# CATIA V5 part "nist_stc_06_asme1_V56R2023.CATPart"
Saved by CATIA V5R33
Part number: NIST PMI STC 06 ASME1
Revision: D
Description: NIST PMI test model downloaded from http://go.usa.gov/mGVm
Bounding box of the stored display mesh (mm): x -152.4 to 152.4, y 0 to 97.79, z -247.65 to 0
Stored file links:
  C:\Users\rla3\OneDrive - NIST\STEP\NIST Test Models\CAx Test Rounds Data\R53J\NIST Files\nist_stc_06_asme1_V56R2023.CATPart
  E:\users\dgn\TPS V5\Import-export annotations\Step\PMI representation 2015\NIST UC\nist_ftc_06_asme1_ct5240_rd.CATPart
  E:\users\dgn\TPS V5\Import-export annotations\Step\PMI representation 2015\NIST UC\CVDHoleParallelCountersink_1_TAG.CATPart
  E:\users\dgn\TPS V5\Import-export annotations\Step\PMI representation 2015\NIST UC\TS_CounterboredHole.CATPart
  C:\Program Files\Dassault Systemes\B32\win_b64\resources\graphic\CATTPSGeneralTolerance.xlsx
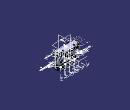
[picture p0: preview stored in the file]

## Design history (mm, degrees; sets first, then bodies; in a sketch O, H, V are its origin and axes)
TTRSSet1
f4a2d38f3ddc11d3a929006094b99c4b_11 "CATTPSSet"
Set1 "Geom_for_MBD_A_notes"
  Plane1: type Equation, A -0.57735, B -0.57735, C 0.57735, Length 229.55, RefPoint vertex [face of Pad1 from Sketch11.L1 | face of Pad1 from Sketch11.L2 | end face of Pad1], RefAxis AxisSystem5
Set2 "MBD_A"
  AxisSystem1 "F1": origin (108.585, 50.8, -209.55), X (-1, 0, 0), Y (0, 1, 0), Z (0, 0, -1)
  AxisSystem2 "F2": origin (36.195, 50.8, -209.55), X (-1, 0, 0), Y (0, 1, 0), Z (0, 0, -1)
  AxisSystem3 "F3": origin (-36.195, 50.8, -209.55), X (-1, 0, 0), Y (0, 1, 0), Z (0, 0, -1)
  AxisSystem4 "F4": origin (-108.585, 50.8, -209.55), X (-1, 0, 0), Y (0, 1, 0), Z (0, 0, -1)
  AxisSystem5 "EAB": origin (0, 0, -209.55), X (-1, 0, 0), Y (0, 0, 1), Z (0, 1, 0)
Set3 "MBD_C"
  AxisSystem6 "DCJ": origin (82.55, 31.75, 0), X (1, 0, 0), Y (0, 0, -1), Z (0, 1, 0)
  AxisSystem7 "DCK": origin (-82.55, 31.75, 0), X (1, 0, 0), Y (0, 0, -1), Z (0, 1, 0)
  AxisSystem8 "DG": origin (76.2, 31.75, -158.75), X (0, 0, -1), Y (-1, 0, 0), Z (0, 1, 0)
  AxisSystem9 "DH": origin (-76.2, 31.75, -158.75), X (0, 0, -1), Y (-1, 0, 0), Z (0, 1, 0)
  Sketch1 on face of Pocket1 from Sketch14.L6, origin (-87.885, 40.9814, 0), H (-0.4226, -0.9063, 0), V (0, 0, 1)
    line L1 (-45.8598, -31.75) -> (-45.8598, 0)
    point P1 (-45.8598, -31.75)
    reference projected point E1 (-45.8598, -31.75) from Sketch9.P5
    vertical: L1 V
    coincidence: P1 E1
  Sketch2 on face of RectPattern2, origin (87.885, 40.9814, 0), H (-0.4226, 0.9063, 0), V (0, 0, 1)
    line L1 (45.8598, -31.75) -> (45.8598, 0)
    point P1 (45.8598, -31.75)
    reference projected point E1 (45.8598, -31.75) from Sketch8.P6
    vertical: L1 V
    coincidence: P1 E1
  Sketch3 on face of RectPattern2, origin (47.7271, -22.2555, 0), H (-0.4226, -0.9063, 0), V (0, 0, 1)
    line L1 (-115.6341, -31.75) -> (-115.6341, 0)
    point P1 (-115.6341, -31.75)
    reference projected point E1 (-115.6341, -31.75) from Sketch8.P5
    vertical: L1 V
    coincidence: P1 E1
  Sketch4 on face of RectPattern2, origin (47.7271, -22.2555, 0), H (-0.4226, -0.9063, 0), V (0, 0, 1)
    projected line E1 (-132.4556, 0) -> (-97.4233, 0) from edge [face of RectPattern2 | face of Pad1 from Sketch11.L1]
    projected line E2 (-132.4556, -31.75) -> (-97.4233, -31.75) from edge [face of Pad1 from Sketch11.L7 | face of RectPattern2]
    line L1 (-97.4233, 0) -> (-115.6341, 0)
    point P5 (-114.9395, 0)
    line L2 (-115.6341, -31.75) -> (-97.4233, -31.75)
    point P6 (-115.6341, -31.75)
    line L3 (-97.4233, 0) -> (-97.4233, -31.75)
    line L4 (-115.6341, 0) -> (-115.6341, -31.75)
    reference projected line E3 (-115.6341, -31.75) -> (-115.6341, 0) from Sketch3
    midpoint: P5 E1
    horizontal: L1 H, L2 H
    coincidence: P6 E2, E3 L4
    vertical: L3 V, L4 V
  Sketch5 on face of RectPattern2, origin (87.885, 40.9814, 0), H (-0.4226, 0.9063, 0), V (0, 0, 1)
    projected line E1 (62.6813, 0) -> (27.6491, 0) from edge [face of Pad1 from Sketch11.L1 | face of RectPattern2]
    projected line E2 (45.8598, 0) -> (27.6491, 0) from edge [face of Pad1 from Sketch11.L1 | face of RectPattern2]
    projected line E3 (27.6491, -31.75) -> (27.6491, 0) from edge [face of RectPattern2 | face of RectPattern2]
    projected line E4 (27.6491, -31.75) -> (62.6813, -31.75) from edge [face of Pad1 from Sketch11.L7 | face of RectPattern2]
    projected line E5 (27.6491, -31.75) -> (45.8598, -31.75) from edge [face of Pad1 from Sketch11.L7 | face of RectPattern2]
    projected line E6 (45.8598, -31.75) -> (45.8598, 0) from Sketch2.L1
  Sketch6 on face of Pocket1 from Sketch14.L6, origin (-87.885, 40.9814, 0), H (-0.4226, -0.9063, 0), V (0, 0, 1)
    projected line E1 (-62.6813, 0) -> (-27.6491, 0) from edge [face of Pocket1 from Sketch14.L6 | face of Pad1 from Sketch11.L1]
    projected line E2 (-45.8598, 0) -> (-27.6491, 0) from edge [face of Pocket1 from Sketch14.L6 | face of Pad1 from Sketch11.L1]
    projected line E3 (-62.6813, -31.75) -> (-27.6491, -31.75) from edge [face of Pad1 from Sketch11.L7 | face of Pocket1 from Sketch14.L6]
    projected line E4 (-45.8598, -31.75) -> (-27.6491, -31.75) from edge [face of Pad1 from Sketch11.L7 | face of Pocket1 from Sketch14.L6]
    projected line E5 (-27.6491, -31.75) -> (-27.6491, 0) from edge [face of Pocket1 from Sketch14.L5 | face of Pocket1 from Sketch14.L6]
    projected line E6 (-45.8598, -31.75) -> (-45.8598, 0) from Sketch1.L1
  Sketch7 on face of Pocket1 from Sketch14.L1, origin (-47.7271, -22.2555, 0), H (-0.4226, 0.9063, 0), V (0, 0, 1)
    projected line E1 (97.4233, -31.75) -> (132.4556, -31.75) from edge [face of Pad1 from Sketch11.L7 | face of Pocket1 from Sketch14.L1]
    projected line E2 (97.4233, -31.75) -> (115.6341, -31.75) from edge [face of Pad1 from Sketch11.L7 | face of Pocket1 from Sketch14.L1]
    projected line E3 (97.4233, -31.75) -> (97.4233, 0) from edge [face of Pocket1 from Sketch14.L1 | face of Pocket1 from Sketch14.L2]
    projected line E4 (132.4556, 0) -> (97.4233, 0) from edge [face of Pad1 from Sketch11.L1 | face of Pocket1 from Sketch14.L1]
    projected line E5 (115.6341, 0) -> (97.4233, 0) from edge [face of Pad1 from Sketch11.L1 | face of Pocket1 from Sketch14.L1]
    projected line E6 (115.6341, -31.75) -> (115.6341, 0) from Sketch10.L1
    construction line L1 through (0, 0) direction (0, 1)
  Sketch8 on face of Pad1 from Sketch11.L7, origin (0, 0, -31.75), H (1, 0, 0), V (0, -1, 0)
    projected line E1 (103.7053, -97.79) -> (88.9, -66.04) from edge [face of Pad1 from Sketch11.L7 | face of RectPattern2]
    projected line E2 (76.2, -66.04) -> (61.3947, -97.79) from edge [face of Pad1 from Sketch11.L7 | face of RectPattern2]
    line L1 (88.9, -66.04) -> (76.2, -66.04)
    line L2 (96.5962, -82.5446) -> (68.5038, -82.5446)
    point P5 (96.5962, -82.5446)
    point P6 (68.5038, -82.5446)
    point P7 (96.5962, -82.5446)
    point P8 (68.5038, -82.5446)
    length L2 = 28.0924
    horizontal: L1 H, L2 H
    coincidence: P5 E1, P6 E2, P7 P5, P8 P6
  Sketch9 on face of Pad1 from Sketch11.L7, origin (0, 0, -31.75), H (1, 0, 0), V (0, -1, 0)
    projected line E1 (-61.3947, -97.79) -> (-76.2, -66.04) from edge [face of Pad1 from Sketch11.L7 | face of Pocket1 from Sketch14.L6]
    projected line E2 (-88.9, -66.04) -> (-103.7053, -97.79) from edge [face of Pad1 from Sketch11.L7 | face of Pocket1 from Sketch14.L1]
    line L1 (-76.2, -66.04) -> (-88.9, -66.04)
    line L2 (-68.5038, -82.5446) -> (-96.5962, -82.5446)
    point P5 (-68.5038, -82.5446)
    point P6 (-96.5962, -82.5446)
    point P7 (-68.5038, -82.5446)
    point P8 (-96.5962, -82.5446)
    length L2 = 28.0924
    horizontal: L1 H, L2 H
    coincidence: P5 E1, P7 P5, P6 E2, P8 P6
  Sketch10 on face of Pocket1 from Sketch14.L1, origin (-47.7271, -22.2555, 0), H (-0.4226, 0.9063, 0), V (0, 0, 1)
    line L1 (115.6341, -31.75) -> (115.6341, 0)
    point P1 (115.6341, -31.75)
    reference projected point E1 (115.6341, -31.75) from Sketch9.P6
    vertical: L1 V
    coincidence: P1 E1
Set4 "MBD_A_B_C"
  AxisSystem10 "DBC": origin (0, 31.75, 0), X (1, 0, 0), Y (0, 0, -1), Z (0, 1, 0)
  AxisSystem11 "ABC": origin (0, 0, 0), X (1, 0, 0), Y (0, 0, -1), Z (0, 1, 0)
Set5
  Plane2: type Offset, RefPlane xy-plane, Offset 247.65, reversed
  Plane3: type Offset, RefPlane zx-plane, Offset 46.99
  Plane4: type Offset, RefPlane yz-plane, Offset 76.2
  Plane5: type Offset, RefPlane yz-plane, Offset 114.3
  Point1: type OnCurve, Support edge [face of Pad1 from Sketch11.L7 | face of Pocket1 from Sketch14.L1], Length 18.2093
  Point2: type OnCurve, Support edge [face of Pad1 from Sketch11.L7 | face of Pocket1 from Sketch14.L6], Length 18.2093
  Point3: type OnCurve, Support edge [face of Pad1 from Sketch11.L7 | face of RectPattern2], Length 18.2093
  Point4: type OnCurve, Support edge [face of Pad1 from Sketch11.L7 | face of RectPattern2], Length 18.2093
  Plane6: type Offset, RefPlane zx-plane, Offset 66.04
  Plane7: type Angle, RefPlane xy-plane, Direction edge [face of Pad1 from Sketch11.L2 | face of Pad1 from Sketch11.L1], Angle 45
  Point5: type OnCurve, Support edge [face of Pad1 from Sketch11.L2 | face of Pad1 from Sketch11.L1], Length 152.4
  Point6: type OnPlane, Support face of Pad1 from Sketch11.L6, H 0, V 0, Direction (-1, 0, 0)
  Point7: type OnCurve, Support edge [face of Fillet1 | face of Pad1 from Sketch11.L6], RefPoint {extremum Reference edge [face of Fillet1 | face of Pad1 from Sketch11.L6], Direction (1, 2, 3)}, Length 65.977
  Point8: type OnCurve, Support edge [face of Fillet1 | face of Pad1 from Sketch11.L6], RefPoint {extremum Reference edge [face of Fillet1 | face of Pad1 from Sketch11.L6], Direction (1, 2, 3)}, Length 65.9892
  Point9: type OnPlane, Support face of Pad1 from Sketch11.L1, H 82.55, V 31.75, Direction (1, 0, 0)
  Point10: type OnPlane, Support face of Pad1 from Sketch11.L1, H -82.55, V 31.75, Direction (1, 0, 0)
  Plane8: type Offset, RefPlane face of Pad1 from Sketch11.L2, Offset 66.04
  Point11: type OnSurface, Support face of Fillet1, Length 0, Direction (-0.9567, 0.021, -0.2904)
  Plane9: type Offset, RefPlane face of Pad1 from Sketch11.L1, Offset 107.95
  Point12: type OnPlane, Support face of Pad1 from Sketch11.L6, H -76.2, V -158.75, Direction (-1, 0, 0)
  Point13: type OnPlane, Support face of Pad1 from Sketch11.L6, H 76.2, V -158.75, Direction (-1, 0, 0)
  Point14: type OnPlane, Support face of Pad1 from Sketch11.L2, H 0, V -209.55, Direction (1, 0, 0)
  Point15 to Point18: stored without definition
  Plane10: type Offset, RefPlane xy-plane, Offset -114.3
Body1 (main body)
  Sketch11 on yz-plane, origin (0, 0, 0), H (0, 1, 0), V (0, 0, 1)
    point P1 (97.79, 0)
    line L1 (97.79, 0) -> (0, 0)
    line L2 (0, 0) -> (0, -234.95)
    line L3 (0, -234.95) -> (50.8, -234.95)
    line L4 (50.8, -234.95) -> (50.8, -209.55)
    line L5 (50.8, -209.55) -> (31.75, -209.55)
    line L6 (31.75, -209.55) -> (31.75, -31.75)
    line L7 (31.75, -31.75) -> (97.79, -31.75)
    line L8 (97.79, -31.75) -> (97.79, 0)
    length L2 = 234.95
    distance L1 L5 = 209.55
    distance L1 L7 = 31.75
    distance L2 L6 = 31.75
    distance L4 L2 = 50.8
    distance L2 L8 = 97.79
    coincidence: P1 H
    horizontal: L1 H, L3 H, L5 H, L7 H
    vertical: L2 V, L4 V, L6 V, L8 V
  Pad1: profile Sketch11, direction (1, 0, 0), length 152.4, mirrored extent
  Sketch12 on yz-plane, origin (0, 0, 0), H (0, 1, 0), V (0, 0, 1)
    line L1 (97.79, -31.75) -> (46.99, -133.35)
    point P1 (97.79, -31.75)
    point P2 (46.99, -133.35)
    line L2 (46.99, -133.35) -> (31.75, -133.35)
    point P3 (31.75, -133.35)
    reference projected point E1 (97.79, -31.75) from vertex [face of Pad1 from Sketch11.L8 | end face of Pad1 | face of Pad1 from Sketch11.L7]
    reference projected point E2 (97.79, -31.75) from vertex [face of Pad1 from Sketch11.L8 | end face of Pad1 | face of Pad1 from Sketch11.L7]
    reference projected line E3 (31.75, -31.75) -> (97.79, -31.75) from edge [face of Pad1 from Sketch11.L7 | end face of Pad1]
    reference projected line E4 (97.79, -31.75) -> (97.79, 0) from edge [face of Pad1 from Sketch11.L8 | end face of Pad1]
    reference intersected line E5 (31.75, -31.75) -> (31.75, -209.55) from face of Pad1 from Sketch11.L6
    distance E3 L2 = 101.6
    distance P2 E4 = 50.8
    coincidence: E1 L1, E2 P1, E5 P3
  Stiffener1: ExtendedProfile Sketch12, ThicknessTop 0, ThicknessValue 25.4
  Sketch13 on Plane2, origin (0, 0, -247.65), H (1, 0, 0), V (0, 1, 0)
    circle A1 centre (108.585, 50.8) radius 22.225
    point P1 (108.585, 50.8)
    reference projected line E1 (-152.4, 0) -> (152.4, 0) from edge [face of Pad1 from Sketch11.L3 | face of Pad1 from Sketch11.L2]
    reference intersected line E2 through (152.4, 0) direction (0, 1) from end face of Pad1
    distance P1 E1 = 50.8
    radius A1 = 22.225
    distance E2 P1 = 43.815
  Pad2: profile Sketch13, direction (0, 0, 1), length 38.1
  RectPattern1: of Pad2, direction 1 instances 4, spacing 72.39, along edge [face of Pad1 from Sketch11.L4 | face of Pad1 from Sketch11.L3] reversed
  Sketch14 on face of Pad1 from Sketch11.L7, origin (0, 0, -31.75), H (1, 0, 0), V (0, -1, 0)
    line L1 (-103.7053, -97.79) -> (-88.9, -66.04)
    point P1 (-88.9, -66.04)
    line L2 (-88.9, -66.04) -> (-88.9, -52.07)
    line L3 (-88.9, -52.07) -> (-76.2, -52.07)
    reference intersected line E1 (-152.4, 0) -> (152.4, 0) from face of Pad1 from Sketch11.L2
    axis line L4 (-82.55, -52.07) -> (-82.55, -133.5251)
    reference intersected line E2 (-152.4, 0) -> (152.4, 0) from face of Pad1 from Sketch11.L2
    point P7 (-76.2, -66.04)
    line L5 (-76.2, -66.04) -> (-76.2, -52.07)
    line L6 (-61.3947, -97.79) -> (-76.2, -66.04)
    reference intersected line E3 through (0, 0) direction (0, 1) from yz-plane
    projected line E4 (-152.4, -97.79) -> (-12.7, -97.79) from edge [face of Pad1 from Sketch11.L8 | face of Pad1 from Sketch11.L7]
    projected line E5 (-103.7053, -97.79) -> (-61.3947, -97.79) from edge [face of Pad1 from Sketch11.L8 | face of Pad1 from Sketch11.L7]
    distance E1 L3 = 52.07
    length L3 = 12.7
    distance L2 L4 = 6.35
    distance E2 P1 = 66.04
    distance E2 P7 = 66.04
    distance L5 L4 = 6.35
    angle L1 L6 = 50
    distance E3 L4 = 82.55
    angle L1 L4 = 25
  Pocket1: profile Sketch14, direction (0, 0, 1), through (limit type 6)
  RectPattern2: of Pocket1, direction 1 instances 2, spacing 165.1, along edge [face of Pad1 from Sketch11.L8 | face of Pad1 from Sketch11.L7]
  Sketch15 on Plane3, origin (0, 46.99, 0), H (0, 0, 1), V (1, 0, 0)
    circle A1 centre (-158.75, 76.2) radius 15.875
    point P1 (-158.75, 76.2)
    reference projected line E1 (0, -152.4) -> (0, 152.4) from edge [face of Pad1 from Sketch11.L1 | face of Pad1 from Sketch11.L8]
    reference intersected line E2 through (0, 0) direction (-1, 0) from yz-plane
    radius A1 = 15.875
    distance E1 P1 = 158.75
    distance E2 P1 = 76.2
  Pad3: profile Sketch15, direction (0, -1, 0), up to face of Pad1 from Sketch11.L6
  Sketch16 on Plane4, origin (76.2, 0, 0), H (0, 1, 0), V (0, 0, 1)
    axis line L1 (47.3647, -158.75) -> (174.207, -158.75)
    reference intersected line E1 (0, 0) -> (97.79, 0) from face of Pad1 from Sketch11.L1
    point P3 (46.99, -174.625)
    line L2 (46.99, -174.625) -> (85.09, -168.275)
    line L3 (85.09, -168.275) -> (85.09, -158.75)
    line L4 (85.09, -158.75) -> (46.99, -158.75)
    reference intersected line E2 (0, -234.95) -> (0, 0) from face of Pad1 from Sketch11.L2
    projected line E3 (46.99, -142.875) -> (46.99, -174.625) from edge [face of Pad3 from Sketch15.A1 | start face of Pad3]
    projected line E4 (46.99, -158.75) -> (46.99, -174.625) from edge [face of Pad3 from Sketch15.A1 | start face of Pad3]
    point P7 (46.99, -174.625)
    distance E1 L1 = 158.75
    distance L3 E2 = 85.09
    length L3 = 9.525
    coincidence: P3 P7, L1 L4
  Shaft1: profile Sketch16, axis Sketch16.L1, angle 360
  Sketch17 on Plane5, origin (114.3, 0, 0), H (0, 1, 0), V (0, 0, 1)
    axis line L1 (-156.5, -107.95) -> (163.5, -107.95)
    arc A1 centre (63.5, -107.95) radius 15.875 from (79.375, -107.95) to (47.625, -107.95) ccw
    point P3 (63.5, -107.95)
    reference projected line E1 (97.79, 0) -> (0, 0) from edge [face of Pad1 from Sketch11.L1 | end face of Pad1]
    reference projected line E2 (0, 0) -> (0, -234.95) from edge [face of Pad1 from Sketch11.L2 | end face of Pad1]
    distance P3 E1 = 107.95
    distance E2 P3 = 63.5
    radius A1 = 15.875
    coincidence: P3 L1
  Shaft2: profile Sketch17, axis Sketch17.L1, angle 360
  Sketch18 on face of Pad1 from Sketch11.L6, origin (0, 31.75, 0), H (-1, 0, 0), V (0, 0, 1)
    circle A1 centre (-114.3, -107.95) radius 11.43
    point P1 (-114.3, -107.95)
    reference intersected line E1 (-152.4, 0) -> (152.4, 0) from face of Pad1 from Sketch11.L1
    reference intersected line E2 through (0, 0) direction (0, -1) from yz-plane
    distance P1 E1 = 107.95
    distance P1 E2 = 114.3
    radius A1 = 11.43
  Pad4: profile Sketch18, direction (0, 1, 0), up to face of Shaft2 from Sketch17.A1
  Sketch19 on face of Pad1 from Sketch11.L7, origin (129.0197, 80.9562, -31.75), H (1, 0, 0), V (0, -1, 0)
    point P1 (-2.0197, 2.2162)
    reference intersected line E1 through (-129.0197, 0) direction (0, 1) from yz-plane
    reference intersected line E2 (23.3803, -16.8338) -> (-281.4197, -16.8338) from face of Pad1 from Sketch11.L8
    distance E1 P1 = 127
    distance P1 E2 = 19.05
  Hole1: placed by Sketch19, at (127, 78.74, -31.75) direction (0, 0, 1), diameter 14.2875, through (limit type 6), counterbore diameter 20.6375, counterbore depth 14.2875
  RectPattern3: of Hole1, direction 1 instances 2, spacing 254, along edge [face of Pad1 from Sketch11.L8 | face of Pad1 from Sketch11.L7] reversed
  Sketch20 on face of Pad1 from Sketch11.L6, origin (123.0782, 31.75, -62.8696), H (1, 0, 0), V (0, 0, -1)
    point P1 (10.2718, -5.7196)
    reference projected line E1 (-275.4782, -62.8696) -> (29.3218, -62.8696) from edge [face of Pad1 from Sketch11.L1 | face of Pad1 from Sketch11.L8]
    reference intersected line E2 through (-123.0782, 0) direction (0, 1) from yz-plane
    distance E1 P1 = 57.15
    distance E2 P1 = 133.35
  Hole2: placed by Sketch20, at (133.35, 31.75, -57.15) direction (0, -1, 0), diameter 10.541, through (limit type 6), counterbore diameter 15.875, counterbore depth 12.7
  RectPattern4: of Hole2, direction 1 instances 2, spacing 266.7, along edge [face of Pad1 from Sketch11.L8 | face of Pad1 from Sketch11.L7] reversed, direction 2 instances 2, spacing 127, along edge [face of Pad1 from Sketch11.L6 | end face of Pad1] reversed
  RectPattern5: of Pad3, Sketch15, Shaft1, Sketch16, direction 1 instances 2, spacing 152.4, along edge [face of Pad1 from Sketch11.L8 | face of Pad1 from Sketch11.L7] reversed, direction 2 instances 2, spacing 127
  Sketch21 on face of Shaft1 from Sketch16.L3, origin (76.2, 85.09, -158.75), H (1, 0, 0), V (0, 0, -1)
    point P1 (0, 0)
    coincidence: P1 O
  Hole3: placed by Sketch21, at (76.2, 85.09, -158.75) direction (0, -1, 0), diameter 6.35, depth 12.7, V-bottom angle 118
  RectPattern6: of Hole3, direction 1 instances 2, spacing 152.4, along edge [face of Pad1 from Sketch11.L4 | face of Pad1 from Sketch11.L3] reversed, direction 2 instances 2, spacing 127
  Fillet1: radius 3.175, on edge [face of Pad1 from Sketch11.L7 | face of Pad1 from Sketch11.L6] (x2); edge [face of Stiffener1 | face of Pad1 from Sketch11.L7]; edge [face of Pad1 from Sketch11.L6 | face of Stiffener1]; edge [face of Stiffener1 from Sketch12.L2 | face of Pad1 from Sketch11.L6]; edge [face of Stiffener1 | face of Pad1 from Sketch11.L6]; edge [face of Pad1 from Sketch11.L7 | face of Stiffener1]; edge [face of Pad1 from Sketch11.L6 | face of RectPattern5]; edge [face of Pad1 from Sketch11.L6 | face of Pad3 from Sketch15.A1]; edge [face of Pad1 from Sketch11.L6 | face of RectPattern1]; edge [face of Pad1 from Sketch11.L4 | face of Pad2 from Sketch13.A1]; edge [face of Pad2 from Sketch13.A1 | face of Pad1 from Sketch11.L4]; edge [face of RectPattern1 | face of Pad1 from Sketch11.L4] (x3); edge [face of Pad1 from Sketch11.L4 | face of RectPattern1] (x3)
  Sketch22 on face of Pad1 from Sketch11.L8, origin (0, 97.79, 0), H (-1, 0, 0), V (0, 0, 1)
    arc A1 centre (0, -15.875) radius 12.7 from (0, -28.575) to (0, -3.175) ccw
    point P1 (0, -15.875)
    reference intersected line E1 through (0, 0) direction (0, -1) from yz-plane
    reference intersected line E2 (152.4, -31.75) -> (-152.4, -31.75) from face of Pad1 from Sketch11.L7
    line L1 (0, -3.175) -> (0, -28.575)
    radius A1 = 12.7
    distance E2 P1 = 15.875
    coincidence: E1 P1, P1 L1
    vertical: L1 V
  Fillet2: radius 12.7, on edge [start face of Pad1 | face of Pad1 from Sketch11.L8]; edge [face of Pad1 from Sketch11.L8 | end face of Pad1]
  Groove1: profile Sketch22, axis Sketch22.L1, angle 360
  Sketch23 on Plane9, origin (0, 97.79, -107.95), H (0, 1, 0), V (1, 0, 0)
    line L1 (-66.04, -114.3) -> (-18.415, -114.3)
    point P1 (-162.8215, -114.3)
    point P2 (-2.54, -114.3)
    line L2 (-66.04, -114.3) -> (-66.04, -125.73)
    line L3 (-66.04, -125.73) -> (-45.3068, -125.73)
    arc A1 centre (-34.29, -114.3) radius 15.875 from (-45.3068, -125.73) to (-18.415, -114.3) ccw
    point P5 (-34.29, -114.3)
    reference intersected line E1 (-66.04, 152.4) -> (-66.04, -152.4) from face of Pad1 from Sketch11.L6
    reference intersected line E2 through (0, 0) direction (-1, 0) from yz-plane
    reference intersected line E3 (-97.79, -152.4) -> (-97.79, 152.4) from face of Pad1 from Sketch11.L2
    radius A1 = 15.875
    distance E2 L1 = 114.3
    distance L1 L3 = 11.43
    distance P5 E3 = 63.5
    horizontal: L1 H, L3 H
    vertical: L2 V
    coincidence: E1 L2, P1 L1, L1 P5
  Shaft3: profile Sketch23, axis Sketch23.L1, angle 360
  Fillet3: radius 3.175, on edge [face of Pad4 from Sketch18.A1 | face of Shaft2 from Sketch17.A1]; edge [face of Pad1 from Sketch11.L6 | face of Pad4 from Sketch18.A1]
  Fillet4: radius 3.175, on edge [face of Shaft3 from Sketch23.A1 | face of Shaft3 from Sketch23.L3]; edge [face of Shaft3 from Sketch23.L3 | face of Pad1 from Sketch11.L6]
  Sketch24 "Main View" on face of Pad1 from Sketch11.L3, origin (0, 0, -234.95), H (-1, 0, 0), V (0, 1, 0)
    point P1 (-27.9401, 6.35)
    point P2 (-14.4332, 7.6694)
    point P3 (-8.1701, 9.8671)
    point P4 (-3.0267, 10.5457)
    point P5 (-1.9341, 9.4532)
    point P6 (-24.8376, 6.35)
    point P7 (-27.9401, 6.35)
    point P8 (-24.8376, 17.5935)
    point P9 (-24.8376, 6.35)
    point P10 (-23.9004, 17.959)
    point P11 (-24.8376, 17.5935)
    point P12 (-14.4332, 7.6694)
    point P13 (-23.9004, 17.959)
    point P14 (-8.1701, 21.35)
    point P15 (-8.1701, 9.8671)
    point P16 (-11.3024, 21.35)
    point P17 (-8.1701, 21.35)
    point P18 (-11.3024, 9.9419)
    point P19 (-11.3024, 21.35)
    point P20 (-12.02, 9.6257)
    point P21 (-11.3024, 9.9419)
    point P22 (-22.2849, 20.7261)
    point P23 (-12.02, 9.6257)
    point P24 (-22.2849, 20.7261)
    point P25 (-27.9401, 18.5121)
    point P26 (-27.9401, 6.35)
    point P27 (-27.9401, 18.5121)
    point P28 (-3.0267, 21.35)
    point P29 (-6.159, 21.35)
    point P30 (-3.0267, 10.5457)
    point P31 (-3.0267, 21.35)
    point P32 (12.7773, 9.4532)
    point P33 (-1.9341, 9.4532)
    point P34 (12.7773, 9.4532)
    point P35 (12.7198, 12.2696)
    point P36 (3.668, 12.2696)
    point P37 (12.7198, 12.2696)
    point P38 (3.3241, 21.35)
    point P39 (3.668, 12.2696)
    point P40 (28.9273, 21.35)
    point P41 (3.3241, 21.35)
    point P42 (28.9273, 18.189)
    point P43 (28.9273, 21.35)
    point P44 (22.5181, 18.189)
    point P45 (28.9273, 18.189)
    point P46 (22.5181, 6.35)
    point P47 (22.5181, 18.189)
    point P48 (19.4156, 6.35)
    point P49 (22.5181, 6.35)
    point P50 (19.4156, 18.189)
    point P51 (19.4156, 6.35)
    point P52 (3.7255, 18.189)
    point P53 (19.4156, 18.189)
    point P54 (3.7255, 18.189)
    point P55 (3.6105, 15.3729)
    point P56 (13.2373, 15.3729)
    point P57 (3.6105, 15.3729)
    point P58 (13.2373, 6.35)
    point P59 (13.2373, 15.3729)
    point P60 (-1.9632, 6.35)
    point P61 (13.2373, 6.35)
    point P62 (-6.159, 10.5457)
    point P63 (-1.9632, 6.35)
    point P64 (-6.159, 21.35)
    point P65 (-6.159, 10.5457)
    line L1 (-6.159, 21.35) -> (-6.159, 10.5457)
    arc A1 centre (-1.9632, 10.5457) radius 4.1957 from (-6.159, 10.5457) to (-1.9632, 6.35) ccw
    line L2 (-1.9632, 6.35) -> (13.2373, 6.35)
    arc A2 centre (12.5188, 10.8615) radius 4.5683 from (13.2373, 6.35) to (13.2373, 15.3729) ccw
    line L3 (13.2373, 15.3729) -> (3.6105, 15.3729)
    arc A3 centre (3.6105, 16.7833) radius 1.4104 from (3.7255, 18.189) to (3.6105, 15.3729) ccw
    line L4 (3.7255, 18.189) -> (19.4156, 18.189)
    line L5 (19.4156, 18.189) -> (19.4156, 6.35)
    line L6 (19.4156, 6.35) -> (22.5181, 6.35)
    line L7 (22.5181, 6.35) -> (22.5181, 18.189)
    line L8 (22.5181, 18.189) -> (28.9273, 18.189)
    line L9 (28.9273, 18.189) -> (28.9273, 21.35)
    line L10 (28.9273, 21.35) -> (3.3241, 21.35)
    arc A4 centre (3.3241, 16.8033) radius 4.5467 from (3.3241, 21.35) to (3.668, 12.2696) ccw
    line L11 (3.668, 12.2696) -> (12.7198, 12.2696)
    arc A5 centre (12.5971, 10.8583) radius 1.4166 from (12.7773, 9.4532) to (12.7198, 12.2696) ccw
    line L12 (12.7773, 9.4532) -> (-1.9341, 9.4532)
    line L13 (-3.0267, 10.5457) -> (-3.0267, 21.35)
    line L14 (-3.0267, 21.35) -> (-6.159, 21.35)
    line L15 (-27.9401, 6.35) -> (-27.9401, 18.5121)
    arc A6 centre (-24.6791, 18.5121) radius 3.261 from (-22.2849, 20.7261) to (-27.9401, 18.5121) ccw
    line L16 (-22.2849, 20.7261) -> (-12.02, 9.6257)
    arc A7 centre (-11.7156, 9.9072) radius 0.4146 from (-12.02, 9.6257) to (-11.3024, 9.9419) ccw
    line L17 (-11.3024, 9.9419) -> (-11.3024, 21.35)
    line L18 (-11.3024, 21.35) -> (-8.1701, 21.35)
    line L19 (-8.1701, 21.35) -> (-8.1701, 9.8671)
    line L20 (-14.4332, 7.6694) -> (-23.9004, 17.959)
    arc A8 centre (-24.2977, 17.5935) radius 0.5399 from (-23.9004, 17.959) to (-24.8376, 17.5935) ccw
    line L21 (-24.8376, 17.5935) -> (-24.8376, 6.35)
    line L22 (-24.8376, 6.35) -> (-27.9401, 6.35)
    arc A9 centre (-1.9341, 10.5457) radius 1.0926 from (-3.0267, 10.5457) to (-1.9341, 9.4532) ccw
    arc A10 centre (-11.6873, 9.8671) radius 3.5171 from (-14.4332, 7.6694) to (-8.1701, 9.8671) ccw
    distance P1 H = 6.35
    distance P1 V = 27.94
    fix: P2, P3, P4, P5, P6, P8, P9, P10, P11, P12, P13, P14, P15, P16, P17, P18, P19, P20, P21, P22, P23, P24, P25, P27, P28, P29, P30, P31, P32, P33, P34, P35, P36, P37, P38, P39, P40, P41, P42, P43, P44, P45, P46, P47, P48, P49, P50, P51, P52, P53, P54, P55, P56, P57, P58, P59, P60, P61, P62, P63, P64, P65, P1, P7, L1, A1, L2, A2, L3, A3, L4, L5, L6, L7, L8, L9, L10, A4, L11, A5, L12, L13, L14, L15, A6, L16, A7, L17, L18, L19, L20, A8, L21, L22, A9, A10, P26
  Pocket2: profile Sketch24, direction (0, 0, 1), length 2.54
  UdfFeature1 "Counterbored Hole": UdfShapeIn Pocket2, UdfInputSpec1 AxisSystem12, UdfInputSpec2 Project1, UdfInputSpec3 Intersect1, DB 7.1374, T 40.64 {= Body2.Offset + (Sketch25.length(L2) * (Body2.Offset / Body2.Offset))}, DFS 10.16, TFS 10.414
  UdfFeature2 "Counterbored Hole": UdfShapeIn UdfFeature1, UdfInputSpec1 AxisSystem14, UdfInputSpec2 Project2, UdfInputSpec3 Intersect2, DB 7.1374, T 40.64 {= Body3.Offset + (Sketch26.length(L2) * (Body3.Offset / Body3.Offset))}, DFS 10.16, TFS 10.414
  UdfFeature3 "Counterbored Hole": UdfShapeIn UdfFeature2, UdfInputSpec1 AxisSystem16, UdfInputSpec2 Project3, UdfInputSpec3 Intersect3, DB 7.1374, T 40.64 {= Body4.Offset + (Sketch27.length(L2) * (Body4.Offset / Body4.Offset))}, DFS 10.16, TFS 10.414
  UdfFeature4 "Counterbored Hole": UdfShapeIn UdfFeature3, UdfInputSpec1 AxisSystem18, UdfInputSpec2 Project4, UdfInputSpec3 Intersect4, DB 7.1374, T 40.64 {= Body5.Offset + (Sketch28.length(L2) * (Body5.Offset / Body5.Offset))}, DFS 10.16, TFS 10.414
Body2 "UDF_Body"
  AxisSystem12 "MainAxisSystem": origin (108.585, 50.8, -250.19), X (-0.9916, -0.1291, 0), Y (-0.1291, 0.9916, 0), Z (0, 0, -1)
  Project1 "Project": ToProject vertex [YZ plane of AxisSystem12 | ZX plane of AxisSystem12 | XY plane of AxisSystem12], Support face of RectPattern1
  Intersect1 "Intersect": ToIntersect1 edge [ZX plane of AxisSystem12 | YZ plane of AxisSystem12], ToIntersect2 face of RectPattern1
  Sketch25 "MainProfileSketch" on ZX plane of AxisSystem12, origin (108.585, 50.8, -250.19), H (0.9916, 0.1291, 0), V (0, 0, -1)
    axis line L1 (0, 0) -> (0, -40.64)
    line L2 (0, -40.64) -> (3.5687, -40.64)
    point P3 (3.5687, -40.64)
    line L3 (3.5687, -40.64) -> (3.5687, -10.414)
    line L4 (5.08, -2) -> (7.08, 0)
    point P4 (7.08, 0)
    line L5 (7.08, 0) -> (7.08, 0)
    line L6 (7.08, 0) -> (7.08, 0)
    line L7 (7.08, 0) -> (0, 0)
    construction line L8 (7.08, 0) -> (0, 0)
    reference projected line E1 through (0, 0) direction (-1, 0) from edge [XY plane of AxisSystem12 | ZX plane of AxisSystem12]
    reference projected line E2 through (0, 0) direction (-1, 0) from edge [XY plane of AxisSystem12 | ZX plane of AxisSystem12]
    reference projected line E3 through (0, 0) direction (0, 1) from edge [ZX plane of AxisSystem12 | YZ plane of AxisSystem12]
    point P7 (-7.08, 0)
    construction line L9 (-11.04, 3.96) -> (-7.08, 0)
    reference projected line E4 through (0, 0) direction (-1, 0) from edge [XY plane of AxisSystem12 | ZX plane of AxisSystem12]
    line L10 (5.08, -10.414) -> (5.08, -2)
    line L11 (3.5687, -10.414) -> (5.08, -10.414)
    arc A1 centre (5.08, -10.414) radius 0 from (5.08, -10.414) to (5.08, -10.414) ccw
    point P9 (5.08, -10.414)
    reference projected line E5 through (0, 0) direction (-1, 0) from edge [XY plane of AxisSystem12 | ZX plane of AxisSystem12]
    construction line L12 (5.08, -10.414) -> (5.08, -10.414)
    construction line L13 (5.08, -10.414) -> (5.08, -10.414)
    point P10 (5.08, -10.414)
    point P11 (5.08, -10.414)
    point P12 (5.08, -10.414)
    line L14 (3.5687, -40.64) -> (3.5687, -40.64)
    point P13 (3.5687, -40.64)
    point P14 (-3.5687, -40.64)
    point P15 (-3.5687, -40.64)
    construction line L15 (-3.5687, -40.64) -> (-3.5687, -40.64)
    point P18 (5.08, -2)
    reference projected line E6 through (0, 0) direction (-1, 0) from edge [XY plane of AxisSystem12 | ZX plane of AxisSystem12]
    point P19 (0, 30)
    angle L4 L9 = 90
    radius about axis L1 L3 = 3.5687 {= Body2.DB / 2}
    distance E1 L2 = 40.64 {= Body2.Offset + (Sketch25.length(L2) * (Body2.Offset / Body2.Offset))}
    length L8 = 7.08 {= sqrt((Body2.AS_H * Body2.AS_H ) + ((Groove2.top_width / 2 + Groove2.AS_ZR ) * (Groove2.top_width / 2 + Groove2.AS_ZR )))}
    angle L8 L5 = 0 {= atan(Body2.AS_H / (Groove2.top_width / 2 + Groove2.AS_ZR ))}
    distance E6 P18 = 2 (reference)
    distance L5 L11 = 10.414
    radius about axis L10 L1 = 5.08 {= Body2.DFS / 2}
    distance E5 P9 = 10.414 {= Body2.TFS - Body2.R}
    radius about axis P9 L1 = 5.08 {= (Body2.DFS / 2) - Body2.R}
    radius A1 = 0 (reference)
    angle L14 L15 = 0
    distance L2 P3 = 0
    length L2 = 3.5687 (reference)
    distance O P19 = 30
    distance P18 P19 V = 32 {= Sketch25.distance(O P19) + Body2.F1}
    coincidence: E4 L5, L1 E3, P11 P10, P12 L11, P19 L1
    perpendicularity: L1 L7, E2 L6, L12 L10, L13 L11
    symmetry: P4 P7 L1, L4 L9 L1, P3 P14 L1, P13 P15 L1, L14 L15 L1
  Groove2 "MainGroove": profile Sketch25, axis Sketch25.L1, angle 360
  Point19 "LimitingAxisSystemOrigin": type OnCurve, Support edge [ZX plane of AxisSystem12 | YZ plane of AxisSystem12], RefPoint Intersect1, Length 0 {= (Sketch25.length(L2)) * (Body2.Offset / Body2.Offset)}
  AxisSystem13 "LimitingAxisSystem": origin (108.585, 50.8, -209.55), X (-0.9916, -0.1291, 0), Y (0.1168, -0.8972, -0.4259), Z (0.055, -0.4224, 0.9048)
Body3 "UDF_Body"
  AxisSystem14 "MainAxisSystem": origin (36.195, 50.8, -250.19), X (-0.9916, -0.1291, 0), Y (-0.1291, 0.9916, 0), Z (0, 0, -1)
  Project2 "Project": ToProject vertex [YZ plane of AxisSystem14 | ZX plane of AxisSystem14 | XY plane of AxisSystem14], Support face of RectPattern1
  Intersect2 "Intersect": ToIntersect1 edge [ZX plane of AxisSystem14 | YZ plane of AxisSystem14], ToIntersect2 face of RectPattern1
  Sketch26 "MainProfileSketch" on ZX plane of AxisSystem14, origin (36.195, 50.8, -250.19), H (0.9916, 0.1291, 0), V (0, 0, -1)
    axis line L1 (0, 0) -> (0, -40.64)
    line L2 (0, -40.64) -> (3.5687, -40.64)
    point P3 (3.5687, -40.64)
    line L3 (3.5687, -40.64) -> (3.5687, -10.414)
    line L4 (5.08, -2) -> (7.08, 0)
    point P4 (7.08, 0)
    line L5 (7.08, 0) -> (7.08, 0)
    line L6 (7.08, 0) -> (7.08, 0)
    line L7 (7.08, 0) -> (0, 0)
    construction line L8 (7.08, 0) -> (0, 0)
    reference projected line E1 through (0, 0) direction (-1, 0) from edge [XY plane of AxisSystem14 | ZX plane of AxisSystem14]
    reference projected line E2 through (0, 0) direction (-1, 0) from edge [XY plane of AxisSystem14 | ZX plane of AxisSystem14]
    reference projected line E3 through (0, 0) direction (0, 1) from edge [ZX plane of AxisSystem14 | YZ plane of AxisSystem14]
    point P7 (-7.08, 0)
    construction line L9 (-11.04, 3.96) -> (-7.08, 0)
    reference projected line E4 through (0, 0) direction (-1, 0) from edge [XY plane of AxisSystem14 | ZX plane of AxisSystem14]
    line L10 (5.08, -10.414) -> (5.08, -2)
    line L11 (3.5687, -10.414) -> (5.08, -10.414)
    arc A1 centre (5.08, -10.414) radius 0 from (5.08, -10.414) to (5.08, -10.414) ccw
    point P9 (5.08, -10.414)
    reference projected line E5 through (0, 0) direction (-1, 0) from edge [XY plane of AxisSystem14 | ZX plane of AxisSystem14]
    construction line L12 (5.08, -10.414) -> (5.08, -10.414)
    construction line L13 (5.08, -10.414) -> (5.08, -10.414)
    point P10 (5.08, -10.414)
    point P11 (5.08, -10.414)
    point P12 (5.08, -10.414)
    line L14 (3.5687, -40.64) -> (3.5687, -40.64)
    point P13 (3.5687, -40.64)
    point P14 (-3.5687, -40.64)
    point P15 (-3.5687, -40.64)
    construction line L15 (-3.5687, -40.64) -> (-3.5687, -40.64)
    point P18 (5.08, -2)
    reference projected line E6 through (0, 0) direction (-1, 0) from edge [XY plane of AxisSystem14 | ZX plane of AxisSystem14]
    point P19 (0, 30)
    angle L4 L9 = 90
    radius about axis L1 L3 = 3.5687 {= Body3.DB / 2}
    distance E1 L2 = 40.64 {= Body3.Offset + (Sketch26.length(L2) * (Body3.Offset / Body3.Offset))}
    length L8 = 7.08 {= sqrt((Body3.AS_H * Body3.AS_H ) + ((Groove3.top_width / 2 + Groove3.AS_ZR ) * (Groove3.top_width / 2 + Groove3.AS_ZR )))}
    angle L8 L5 = 0 {= atan(Body3.AS_H / (Groove3.top_width / 2 + Groove3.AS_ZR ))}
    distance E6 P18 = 2 (reference)
    distance L5 L11 = 10.414
    radius about axis L10 L1 = 5.08 {= Body3.DFS / 2}
    distance E5 P9 = 10.414 {= Body3.TFS - Body3.R}
    radius about axis P9 L1 = 5.08 {= (Body3.DFS / 2) - Body3.R}
    radius A1 = 0 (reference)
    angle L14 L15 = 0
    distance L2 P3 = 0
    length L2 = 3.5687 (reference)
    distance O P19 = 30
    distance P18 P19 V = 32 {= Sketch26.distance(O P19) + Body3.F1}
    coincidence: E4 L5, L1 E3, P11 P10, P12 L11, P19 L1
    perpendicularity: L1 L7, E2 L6, L12 L10, L13 L11
    symmetry: P4 P7 L1, L4 L9 L1, P3 P14 L1, P13 P15 L1, L14 L15 L1
  Groove3 "MainGroove": profile Sketch26, axis Sketch26.L1, angle 360
  Point20 "LimitingAxisSystemOrigin": type OnCurve, Support edge [ZX plane of AxisSystem14 | YZ plane of AxisSystem14], RefPoint Intersect2, Length 0 {= (Sketch26.length(L2)) * (Body3.Offset / Body3.Offset)}
  AxisSystem15 "LimitingAxisSystem": origin (36.195, 50.8, -209.55), X (-0.9916, -0.1291, 0), Y (0.1168, -0.8972, -0.4259), Z (0.055, -0.4224, 0.9048)
Body4 "UDF_Body"
  AxisSystem16 "MainAxisSystem": origin (-36.195, 50.8, -250.19), X (-0.9916, -0.1291, 0), Y (-0.1291, 0.9916, 0), Z (0, 0, -1)
  Project3 "Project": ToProject vertex [YZ plane of AxisSystem16 | ZX plane of AxisSystem16 | XY plane of AxisSystem16], Support face of RectPattern1
  Intersect3 "Intersect": ToIntersect1 edge [ZX plane of AxisSystem16 | YZ plane of AxisSystem16], ToIntersect2 face of RectPattern1
  Sketch27 "MainProfileSketch" on ZX plane of AxisSystem16, origin (-36.195, 50.8, -250.19), H (0.9916, 0.1291, 0), V (0, 0, -1)
    axis line L1 (0, 0) -> (0, -40.64)
    line L2 (0, -40.64) -> (3.5687, -40.64)
    point P3 (3.5687, -40.64)
    line L3 (3.5687, -40.64) -> (3.5687, -10.414)
    line L4 (5.08, -2) -> (7.08, 0)
    point P4 (7.08, 0)
    line L5 (7.08, 0) -> (7.08, 0)
    line L6 (7.08, 0) -> (7.08, 0)
    line L7 (7.08, 0) -> (0, 0)
    construction line L8 (7.08, 0) -> (0, 0)
    reference projected line E1 through (0, 0) direction (-1, 0) from edge [XY plane of AxisSystem16 | ZX plane of AxisSystem16]
    reference projected line E2 through (0, 0) direction (-1, 0) from edge [XY plane of AxisSystem16 | ZX plane of AxisSystem16]
    reference projected line E3 through (0, 0) direction (0, 1) from edge [ZX plane of AxisSystem16 | YZ plane of AxisSystem16]
    point P7 (-7.08, 0)
    construction line L9 (-11.04, 3.96) -> (-7.08, 0)
    reference projected line E4 through (0, 0) direction (-1, 0) from edge [XY plane of AxisSystem16 | ZX plane of AxisSystem16]
    line L10 (5.08, -10.414) -> (5.08, -2)
    line L11 (3.5687, -10.414) -> (5.08, -10.414)
    arc A1 centre (5.08, -10.414) radius 0 from (5.08, -10.414) to (5.08, -10.414) ccw
    point P9 (5.08, -10.414)
    reference projected line E5 through (0, 0) direction (-1, 0) from edge [XY plane of AxisSystem16 | ZX plane of AxisSystem16]
    construction line L12 (5.08, -10.414) -> (5.08, -10.414)
    construction line L13 (5.08, -10.414) -> (5.08, -10.414)
    point P10 (5.08, -10.414)
    point P11 (5.08, -10.414)
    point P12 (5.08, -10.414)
    line L14 (3.5687, -40.64) -> (3.5687, -40.64)
    point P13 (3.5687, -40.64)
    point P14 (-3.5687, -40.64)
    point P15 (-3.5687, -40.64)
    construction line L15 (-3.5687, -40.64) -> (-3.5687, -40.64)
    point P18 (5.08, -2)
    reference projected line E6 through (0, 0) direction (-1, 0) from edge [XY plane of AxisSystem16 | ZX plane of AxisSystem16]
    point P19 (0, 30)
    angle L4 L9 = 90
    radius about axis L1 L3 = 3.5687 {= Body4.DB / 2}
    distance E1 L2 = 40.64 {= Body4.Offset + (Sketch27.length(L2) * (Body4.Offset / Body4.Offset))}
    length L8 = 7.08 {= sqrt((Body4.AS_H * Body4.AS_H ) + ((Groove4.top_width / 2 + Groove4.AS_ZR ) * (Groove4.top_width / 2 + Groove4.AS_ZR )))}
    angle L8 L5 = 0 {= atan(Body4.AS_H / (Groove4.top_width / 2 + Groove4.AS_ZR ))}
    distance E6 P18 = 2 (reference)
    distance L5 L11 = 10.414
    radius about axis L10 L1 = 5.08 {= Body4.DFS / 2}
    distance E5 P9 = 10.414 {= Body4.TFS - Body4.R}
    radius about axis P9 L1 = 5.08 {= (Body4.DFS / 2) - Body4.R}
    radius A1 = 0 (reference)
    angle L14 L15 = 0
    distance L2 P3 = 0
    length L2 = 3.5687 (reference)
    distance O P19 = 30
    distance P18 P19 V = 32 {= Sketch27.distance(O P19) + Body4.F1}
    coincidence: E4 L5, L1 E3, P11 P10, P12 L11, P19 L1
    perpendicularity: L1 L7, E2 L6, L12 L10, L13 L11
    symmetry: P4 P7 L1, L4 L9 L1, P3 P14 L1, P13 P15 L1, L14 L15 L1
  Groove4 "MainGroove": profile Sketch27, axis Sketch27.L1, angle 360
  Point21 "LimitingAxisSystemOrigin": type OnCurve, Support edge [ZX plane of AxisSystem16 | YZ plane of AxisSystem16], RefPoint Intersect3, Length 0 {= (Sketch27.length(L2)) * (Body4.Offset / Body4.Offset)}
  AxisSystem17 "LimitingAxisSystem": origin (-36.195, 50.8, -209.55), X (-0.9916, -0.1291, 0), Y (0.1168, -0.8972, -0.4259), Z (0.055, -0.4224, 0.9048)
Body5 "UDF_Body"
  AxisSystem18 "MainAxisSystem": origin (-108.585, 50.8, -250.19), X (-0.9916, -0.1291, 0), Y (-0.1291, 0.9916, 0), Z (0, 0, -1)
  Project4 "Project": ToProject vertex [YZ plane of AxisSystem18 | ZX plane of AxisSystem18 | XY plane of AxisSystem18], Support face of RectPattern1
  Intersect4 "Intersect": ToIntersect1 edge [ZX plane of AxisSystem18 | YZ plane of AxisSystem18], ToIntersect2 face of RectPattern1
  Sketch28 "MainProfileSketch" on ZX plane of AxisSystem18, origin (-108.585, 50.8, -250.19), H (0.9916, 0.1291, 0), V (0, 0, -1)
    axis line L1 (0, 0) -> (0, -40.64)
    line L2 (0, -40.64) -> (3.5687, -40.64)
    point P3 (3.5687, -40.64)
    line L3 (3.5687, -40.64) -> (3.5687, -10.414)
    line L4 (5.08, -2) -> (7.08, 0)
    point P4 (7.08, 0)
    line L5 (7.08, 0) -> (7.08, 0)
    line L6 (7.08, 0) -> (7.08, 0)
    line L7 (7.08, 0) -> (0, 0)
    construction line L8 (7.08, 0) -> (0, 0)
    reference projected line E1 through (0, 0) direction (-1, 0) from edge [XY plane of AxisSystem18 | ZX plane of AxisSystem18]
    reference projected line E2 through (0, 0) direction (-1, 0) from edge [XY plane of AxisSystem18 | ZX plane of AxisSystem18]
    reference projected line E3 through (0, 0) direction (0, 1) from edge [ZX plane of AxisSystem18 | YZ plane of AxisSystem18]
    point P7 (-7.08, 0)
    construction line L9 (-11.04, 3.96) -> (-7.08, 0)
    reference projected line E4 through (0, 0) direction (-1, 0) from edge [XY plane of AxisSystem18 | ZX plane of AxisSystem18]
    line L10 (5.08, -10.414) -> (5.08, -2)
    line L11 (3.5687, -10.414) -> (5.08, -10.414)
    arc A1 centre (5.08, -10.414) radius 0 from (5.08, -10.414) to (5.08, -10.414) ccw
    point P9 (5.08, -10.414)
    reference projected line E5 through (0, 0) direction (-1, 0) from edge [XY plane of AxisSystem18 | ZX plane of AxisSystem18]
    construction line L12 (5.08, -10.414) -> (5.08, -10.414)
    construction line L13 (5.08, -10.414) -> (5.08, -10.414)
    point P10 (5.08, -10.414)
    point P11 (5.08, -10.414)
    point P12 (5.08, -10.414)
    line L14 (3.5687, -40.64) -> (3.5687, -40.64)
    point P13 (3.5687, -40.64)
    point P14 (-3.5687, -40.64)
    point P15 (-3.5687, -40.64)
    construction line L15 (-3.5687, -40.64) -> (-3.5687, -40.64)
    point P18 (5.08, -2)
    reference projected line E6 through (0, 0) direction (-1, 0) from edge [XY plane of AxisSystem18 | ZX plane of AxisSystem18]
    point P19 (0, 30)
    angle L4 L9 = 90
    radius about axis L1 L3 = 3.5687 {= Body5.DB / 2}
    distance E1 L2 = 40.64 {= Body5.Offset + (Sketch28.length(L2) * (Body5.Offset / Body5.Offset))}
    length L8 = 7.08 {= sqrt((Body5.AS_H * Body5.AS_H ) + ((Groove5.top_width / 2 + Groove5.AS_ZR ) * (Groove5.top_width / 2 + Groove5.AS_ZR )))}
    angle L8 L5 = 0 {= atan(Body5.AS_H / (Groove5.top_width / 2 + Groove5.AS_ZR ))}
    distance E6 P18 = 2 (reference)
    distance L5 L11 = 10.414
    radius about axis L10 L1 = 5.08 {= Body5.DFS / 2}
    distance E5 P9 = 10.414 {= Body5.TFS - Body5.R}
    radius about axis P9 L1 = 5.08 {= (Body5.DFS / 2) - Body5.R}
    radius A1 = 0 (reference)
    angle L14 L15 = 0
    distance L2 P3 = 0
    length L2 = 3.5687 (reference)
    distance O P19 = 30
    distance P18 P19 V = 32 {= Sketch28.distance(O P19) + Body5.F1}
    coincidence: E4 L5, L1 E3, P11 P10, P12 L11, P19 L1
    perpendicularity: L1 L7, E2 L6, L12 L10, L13 L11
    symmetry: P4 P7 L1, L4 L9 L1, P3 P14 L1, P13 P15 L1, L14 L15 L1
  Groove5 "MainGroove": profile Sketch28, axis Sketch28.L1, angle 360
  Point22 "LimitingAxisSystemOrigin": type OnCurve, Support edge [ZX plane of AxisSystem18 | YZ plane of AxisSystem18], RefPoint Intersect4, Length 0 {= (Sketch28.length(L2)) * (Body5.Offset / Body5.Offset)}
  AxisSystem19 "LimitingAxisSystem": origin (-108.585, 50.8, -209.55), X (-0.9916, -0.1291, 0), Y (0.1168, -0.8972, -0.4259), Z (0.055, -0.4224, 0.9048)
Relations
  Body2.W1 = Sketch25.angle(L4 L9)
  Body2.W3 = Sketch25.angle(L14 L15)
  Body2.TFS = Sketch25.distance(L5 L11)
  Body2.T = Sketch25.distance(E1 L2)
  Body2.F3 = Sketch25.distance(L2 P3)
  Groove2.top_width = (`Sketch25.radius about axis(L10 L1)` * 2) + (2 * tan(Sketch25.angle(L4 L9) / 2) * Sketch25.distance(E6 P18) )
  rule "AS_ZR":
    /*Rule created by AKNOPP 22.05.2006*/
    Groove2.AS_ZR = Body2.AS_D - Groove2.top_width
    if (Body2.AS_D == 0mm)
    {
    	Groove2.AS_ZR = 0mm
    }
    else
    {
    	Groove2.AS_ZR = (Body2.AS_D / 2) - (Groove2.top_width / 2)
    }
  Body3.W1 = Sketch26.angle(L4 L9)
  Body3.W3 = Sketch26.angle(L14 L15)
  Body3.TFS = Sketch26.distance(L5 L11)
  Body3.T = Sketch26.distance(E1 L2)
  Body3.F3 = Sketch26.distance(L2 P3)
  Groove3.top_width = (`Sketch26.radius about axis(L10 L1)` * 2) + (2 * tan(Sketch26.angle(L4 L9) / 2) * Sketch26.distance(E6 P18) )
  rule "AS_ZR":
    /*Rule created by AKNOPP 22.05.2006*/
    Groove3.AS_ZR = Body3.AS_D - Groove3.top_width
    if (Body3.AS_D == 0mm)
    {
    	Groove3.AS_ZR = 0mm
    }
    else
    {
    	Groove3.AS_ZR = (Body3.AS_D / 2) - (Groove3.top_width / 2)
    }
  Body4.W1 = Sketch27.angle(L4 L9)
  Body4.W3 = Sketch27.angle(L14 L15)
  Body4.TFS = Sketch27.distance(L5 L11)
  Body4.T = Sketch27.distance(E1 L2)
  Body4.F3 = Sketch27.distance(L2 P3)
  Groove4.top_width = (`Sketch27.radius about axis(L10 L1)` * 2) + (2 * tan(Sketch27.angle(L4 L9) / 2) * Sketch27.distance(E6 P18) )
  rule "AS_ZR":
    /*Rule created by AKNOPP 22.05.2006*/
    Groove4.AS_ZR = Body4.AS_D - Groove4.top_width
    if (Body4.AS_D == 0mm)
    {
    	Groove4.AS_ZR = 0mm
    }
    else
    {
    	Groove4.AS_ZR = (Body4.AS_D / 2) - (Groove4.top_width / 2)
    }
  Body5.W1 = Sketch28.angle(L4 L9)
  Body5.W3 = Sketch28.angle(L14 L15)
  Body5.TFS = Sketch28.distance(L5 L11)
  Body5.T = Sketch28.distance(E1 L2)
  Body5.F3 = Sketch28.distance(L2 P3)
  Groove5.top_width = (`Sketch28.radius about axis(L10 L1)` * 2) + (2 * tan(Sketch28.angle(L4 L9) / 2) * Sketch28.distance(E6 P18) )
  rule "AS_ZR":
    /*Rule created by AKNOPP 22.05.2006*/
    Groove5.AS_ZR = Body5.AS_D - Groove5.top_width
    if (Body5.AS_D == 0mm)
    {
    	Groove5.AS_ZR = 0mm
    }
    else
    {
    	Groove5.AS_ZR = (Body5.AS_D / 2) - (Groove5.top_width / 2)
    }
